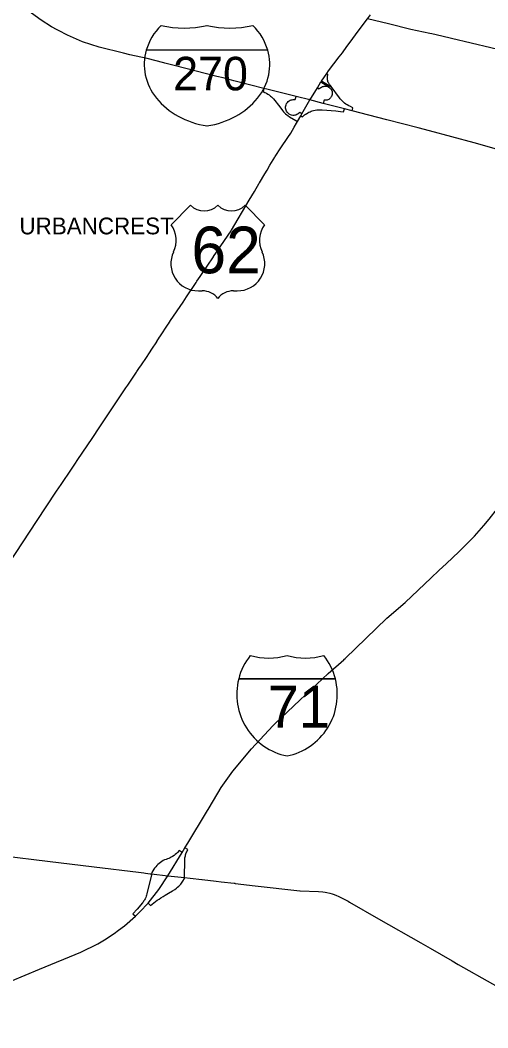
# Model space of a CAD drawing. Extents: x -1146 to -445, y -1283 to -822.
# Drawn here: x -959.3 to -924.4, y -1179.7 to -1104.6 of the extents above; entities that cross this region are included whole.
import ezdxf

# ---------------------------------------------------------------- set-up
doc = ezdxf.new("R2010")
doc.units = 0
for name, color, linetype in [('GM_X_Corporation_Text', 7, 'Continuous'), ('GM_X_Interchange_Ramps', 7, 'Continuous'), ('GM_X_Interstate_Route', 7, 'Continuous'), ('GM_X_Interstate_Shield', 7, 'Continuous'), ('GM_X_State_Route', 7, 'Continuous'), ('GM_X_Township', 7, 'Continuous'), ('GM_X_US_Route', 7, 'Continuous'), ('GM_X_US_Shield', 7, 'Continuous')]:
    doc.layers.add(name, color=color, linetype=linetype)

msp = doc.modelspace()

# ---------------------------------------------------------------- linework, layer by layer
at = {"layer": 'GM_X_Interchange_Ramps'}
for points in [[(-934.577, -1111.334), (-934.518, -1111.105), (-934.687, -1111.022), (-934.822, -1110.957), (-934.929, -1110.897), (-935.031, -1110.833), (-935.125, -1110.764), (-935.208, -1110.697), (-935.287, -1110.627), (-935.386, -1110.527), (-935.45, -1110.456), (-935.513, -1110.378), (-936.138, -1109.534), (-936.194, -1109.458), (-936.261, -1109.375), (-936.313, -1109.289), (-936.345, -1109.221), (-936.369, -1109.158), (-936.386, -1109.096), (-936.398, -1109.04), (-936.407, -1108.961), (-936.409, -1108.886), (-936.403, -1108.799), (-936.37, -1108.618), (-936.453, -1108.558)], [(-941.149, -1109.671), (-941.211, -1109.908), (-941.071, -1109.97), (-940.958, -1110.029), (-940.856, -1110.09), (-940.763, -1110.153), (-940.657, -1110.234), (-940.587, -1110.295), (-940.514, -1110.365), (-940.431, -1110.454), (-939.969, -1111.047), (-939.767, -1111.309), (-939.687, -1111.405), (-939.614, -1111.484), (-939.535, -1111.557), (-939.447, -1111.63), (-939.373, -1111.685), (-939.235, -1111.785), (-938.77, -1112.068), (-938.647, -1112.141)], [(-937.158, -1109.621), (-937.021, -1109.706), (-936.971, -1109.658), (-936.91, -1109.612), (-936.845, -1109.572), (-936.772, -1109.536), (-936.706, -1109.515), (-936.643, -1109.504), (-936.572, -1109.5), (-936.491, -1109.507), (-936.411, -1109.527), (-936.355, -1109.549), (-936.298, -1109.581), (-936.243, -1109.62), (-936.197, -1109.663), (-936.159, -1109.707), (-936.125, -1109.757), (-936.094, -1109.818), (-936.068, -1109.894), (-936.055, -1109.958), (-936.051, -1110.053), (-936.059, -1110.121), (-936.08, -1110.202), (-936.111, -1110.274), (-936.146, -1110.33), (-936.187, -1110.382), (-936.229, -1110.424), (-936.268, -1110.455), (-936.317, -1110.487), (-936.377, -1110.516), (-936.439, -1110.537), (-936.483, -1110.547), (-936.54, -1110.555), (-936.659, -1110.555), (-936.719, -1110.793)], [(-936.897, -1109.169), (-936.82, -1109.222), (-936.277, -1109.545), (-936.298, -1109.581)], [(-936.138, -1109.534), (-936.159, -1109.55), (-936.791, -1109.173), (-936.865, -1109.122)], [(-938.312, -1111.557), (-938.463, -1111.467), (-938.593, -1111.569), (-938.688, -1111.625), (-938.762, -1111.654), (-938.838, -1111.673), (-938.918, -1111.682), (-939.002, -1111.679), (-939.08, -1111.666), (-939.161, -1111.64), (-939.265, -1111.586), (-939.344, -1111.524), (-939.415, -1111.445), (-939.466, -1111.365), (-939.499, -1111.288), (-939.52, -1111.217), (-939.53, -1111.148), (-939.531, -1111.046), (-939.519, -1110.962), (-939.494, -1110.88), (-939.456, -1110.799), (-939.391, -1110.707), (-939.331, -1110.646), (-939.255, -1110.589), (-939.18, -1110.55), (-939.114, -1110.525), (-939.042, -1110.508), (-938.969, -1110.5), (-938.815, -1110.506), (-938.75, -1110.271)], [(-938.401, -1111.712), (-938.279, -1111.784), (-938.186, -1111.701), (-938.119, -1111.647), (-938.051, -1111.597), (-937.984, -1111.552), (-937.881, -1111.49), (-937.787, -1111.442), (-937.705, -1111.404), (-937.626, -1111.372), (-937.544, -1111.344), (-937.451, -1111.317), (-937.322, -1111.287), (-937.205, -1111.268), (-937.063, -1111.256), (-936.936, -1111.254), (-936.809, -1111.26), (-935.789, -1111.352), (-935.424, -1111.384), (-935.204, -1111.426), (-935.141, -1111.186)], [(-947.251, -1166.639), (-947.465, -1166.508), (-947.599, -1166.652), (-947.676, -1166.726), (-947.762, -1166.8), (-947.857, -1166.872), (-947.969, -1166.947), (-948.058, -1166.998), (-948.152, -1167.046), (-948.251, -1167.09), (-948.353, -1167.129), (-948.447, -1167.16), (-948.555, -1167.203), (-948.654, -1167.25), (-948.763, -1167.311), (-948.867, -1167.379), (-948.965, -1167.454), (-949.062, -1167.539), (-949.141, -1167.62), (-949.218, -1167.709), (-949.301, -1167.822), (-949.361, -1167.891), (-949.438, -1168.006), (-949.508, -1168.129), (-949.537, -1168.241)], [(-947.073, -1168.499), (-947.069, -1168.386), (-947.058, -1167.328), (-947.056, -1167.218), (-947.05, -1167.128), (-947.041, -1167.054), (-947.026, -1166.964), (-947.01, -1166.889), (-946.991, -1166.814), (-946.968, -1166.741), (-946.942, -1166.666), (-946.912, -1166.592), (-946.835, -1166.424), (-947.046, -1166.295)], [(-949.537, -1168.241), (-949.546, -1168.32), (-949.88, -1169.737), (-949.907, -1169.828), (-949.935, -1169.905), (-949.971, -1169.993), (-950.017, -1170.09), (-950.056, -1170.163), (-950.092, -1170.225), (-950.126, -1170.278), (-950.166, -1170.337), (-950.205, -1170.39), (-950.6, -1170.882), (-950.922, -1171.216), (-950.734, -1171.403)], [(-949.792, -1170.423), (-949.621, -1170.594), (-949.487, -1170.488), (-949.367, -1170.396), (-949.227, -1170.294), (-949.102, -1170.205), (-948.971, -1170.115), (-948.832, -1170.023), (-948.665, -1169.918), (-948.517, -1169.828), (-948.389, -1169.753), (-948.264, -1169.682), (-947.977, -1169.511), (-947.8, -1169.405), (-947.679, -1169.317), (-947.589, -1169.243), (-947.495, -1169.154), (-947.422, -1169.077), (-947.358, -1169.002), (-947.301, -1168.928), (-947.189, -1168.777), (-947.081, -1168.575), (-947.073, -1168.499)]]:
    msp.add_lwpolyline(points, dxfattribs=at)
at = {"layer": 'GM_X_Interstate_Route'}
for points in [[(-956.563, -1105.311), (-957.01, -1105.076), (-957.775, -1104.578), (-958.499, -1104.045), (-959.23, -1103.43), (-959.413, -1103.252)], [(-951.142, -1107.157), (-951.627, -1107.051), (-953.431, -1106.586), (-954.68, -1106.197), (-955.794, -1105.705), (-956.477, -1105.356), (-956.563, -1105.311)], [(-948.546, -1107.78), (-948.607, -1107.764), (-949.866, -1107.436), (-951.142, -1107.157)], [(-943.923, -1108.959), (-944.19, -1108.89), (-944.667, -1108.768), (-947.839, -1107.964), (-948.546, -1107.78)], [(-943.394, -1109.095), (-943.923, -1108.959)], [(-940.931, -1109.726), (-941.149, -1109.671), (-942.131, -1109.42), (-943.394, -1109.095)], [(-937.723, -1110.53), (-938.75, -1110.271), (-940.931, -1109.726)], [(-918.68, -1116.588), (-919.128, -1116.32), (-920.698, -1115.452), (-921.421, -1115.142), (-922.643, -1114.621), (-923.8, -1114.196), (-925.452, -1113.725), (-928.801, -1112.823), (-929.653, -1112.604), (-931.972, -1112.008), (-933.318, -1111.662), (-934.577, -1111.334), (-935.141, -1111.186), (-936.719, -1110.793), (-937.723, -1110.53)], [(-924.752, -1142.273), (-924.336, -1141.79), (-923.11, -1140.191), (-922.672, -1139.564), (-921.629, -1137.894), (-921.487, -1137.641)], [(-928.092, -1145.619), (-927.535, -1145.096), (-926.609, -1144.216), (-925.429, -1143.058), (-924.752, -1142.273)], [(-935.194, -1152.265), (-935.094, -1152.176), (-931.983, -1149.176), (-930.614, -1148.014), (-928.67, -1146.162), (-928.092, -1145.619)], [(-940.482, -1157.202), (-940.421, -1157.135), (-940.313, -1157.017), (-938.472, -1155.287), (-936.354, -1153.288), (-935.196, -1152.267), (-935.194, -1152.265)], [(-945.234, -1163.319), (-944.328, -1161.809), (-943.473, -1160.577), (-942.069, -1158.924), (-940.482, -1157.202)], [(-946.837, -1165.952), (-945.428, -1163.642), (-945.234, -1163.319)], [(-948.312, -1168.38), (-947.251, -1166.639), (-947.046, -1166.295), (-946.837, -1165.952)], [(-951.99, -1172.446), (-951.542, -1172.113), (-950.734, -1171.403), (-950.396, -1171.069), (-949.792, -1170.423), (-948.991, -1169.405), (-948.312, -1168.38)], [(-968.533, -1179.721), (-968.41, -1179.67), (-965.26, -1178.386), (-961.115, -1176.691), (-957.891, -1175.351), (-954.804, -1174.074), (-953.551, -1173.453), (-952.931, -1173.094), (-952.659, -1172.914)], [(-952.659, -1172.914), (-952.311, -1172.684), (-951.99, -1172.446)]]:
    msp.add_lwpolyline(points, dxfattribs=at)
at = {"layer": 'GM_X_Interstate_Shield'}
for p, q in [((-940.864, -1106.804), (-949.929, -1106.804)), ((-940.864, -1106.804), (-949.929, -1106.804)), ((-943.03, -1153.705), (-935.816, -1153.705)), ((-935.816, -1153.705), (-943.03, -1153.705)), ((-935.816, -1153.705), (-943.03, -1153.705))]:
    msp.add_line(p, q, dxfattribs=at)
for centre, start, end in [((-938.486, -1154.854), 141.66896, 165.80665), ((-940.793, -1147.464), 253.00908, 286.99093), ((-938.053, -1147.464), 253.00908, 286.99093), ((-940.361, -1154.854), 14.19335, 38.33104), ((-938.486, -1154.854), 165.80665, 258.46304), ((-940.361, -1154.854), 281.53696, 14.19335)]:
    msp.add_arc(centre, 4.688, start, end, dxfattribs=at)
for centre, start_param, end_param in [((-944.224, -1107.875), 2.47259, 2.911027), ((-947.108, -1100.485), 4.415841, 5.008937), ((-943.684, -1100.485), 4.415841, 5.008937), ((-946.568, -1107.875), 0.230566, 0.669003), ((-944.224, -1107.875), 2.911027, 4.511031), ((-946.568, -1107.875), 4.913747, 6.513751)]:
    msp.add_ellipse(centre, major_axis=(5.859, 0), ratio=0.8, start_param=start_param, end_param=end_param, dxfattribs=at)
at = {"layer": 'GM_X_State_Route'}
for points in [[(-968.164, -1166.022), (-968.04, -1166.038), (-961.891, -1166.75), (-960.545, -1166.906), (-957.293, -1167.291), (-953.811, -1167.708), (-950.505, -1168.12), (-950.108, -1168.165)], [(-950.108, -1168.165), (-949.977, -1168.18), (-949.647, -1168.226)], [(-949.647, -1168.226), (-949.537, -1168.241), (-948.312, -1168.38), (-947.073, -1168.499), (-946.659, -1168.565)], [(-946.659, -1168.565), (-945.793, -1168.663), (-945.755, -1168.668)], [(-945.755, -1168.668), (-944.722, -1168.792)], [(-944.722, -1168.792), (-944.345, -1168.837), (-944.335, -1168.838)], [(-944.335, -1168.838), (-943.36, -1168.938), (-943.309, -1168.944), (-943.3, -1168.945)], [(-943.3, -1168.945), (-941.803, -1169.121), (-938.48, -1169.502), (-938.442, -1169.506), (-937.065, -1169.548), (-936.762, -1169.578), (-936.575, -1169.603)], [(-936.575, -1169.603), (-936.446, -1169.619), (-936.229, -1169.678), (-936.054, -1169.73), (-935.904, -1169.778), (-935.73, -1169.843), (-935.614, -1169.895), (-935.219, -1170.102)], [(-935.219, -1170.102), (-934.867, -1170.287)], [(-934.867, -1170.287), (-934.771, -1170.337), (-932.602, -1171.587), (-929.445, -1173.37), (-928.757, -1173.791), (-927.098, -1174.721), (-926.651, -1174.988), (-924.094, -1176.438), (-922.913, -1177.105)]]:
    msp.add_lwpolyline(points, dxfattribs=at)
at = {"layer": 'GM_X_Township'}
msp.add_lwpolyline([(-921.29, -1107.327), (-927.148, -1105.948), (-927.883, -1105.775), (-928.631, -1105.599), (-928.778, -1105.565), (-930.186, -1105.266), (-931.853, -1104.841), (-933.424, -1104.471)], dxfattribs=at)
at = {"layer": 'GM_X_US_Route'}
for points in [[(-934.041, -1105.296), (-933.424, -1104.471), (-933.2, -1104.178)], [(-934.957, -1106.533), (-934.801, -1106.312), (-934.041, -1105.296)], [(-935.534, -1107.324), (-935.295, -1107.01), (-934.957, -1106.533)], [(-937.61, -1110.348), (-937.158, -1109.621), (-936.897, -1109.169), (-936.865, -1109.122), (-936.453, -1108.558), (-936.32, -1108.352), (-935.534, -1107.324)], [(-938.712, -1112.247), (-938.647, -1112.141), (-938.401, -1111.712), (-938.312, -1111.557), (-937.723, -1110.53), (-937.61, -1110.348)], [(-939.36, -1113.331), (-939.137, -1113.003), (-938.895, -1112.546), (-938.712, -1112.247)], [(-945.852, -1123.608), (-944.923, -1122.221), (-944.908, -1122.199), (-943.594, -1120.277), (-943.568, -1120.234), (-942.244, -1118.007), (-941.851, -1117.345), (-941.494, -1116.744), (-941.478, -1116.717), (-941.085, -1116.05), (-940.916, -1115.765), (-940.703, -1115.402), (-940.344, -1114.793), (-940.307, -1114.737), (-939.88, -1114.098), (-939.36, -1113.331)], [(-948.279, -1127.233), (-948.111, -1126.981), (-947.183, -1125.596), (-946.923, -1125.208), (-946.203, -1124.132), (-946.146, -1124.047)], [(-946.146, -1124.047), (-945.909, -1123.692), (-945.852, -1123.608)], [(-949.143, -1128.563), (-949.133, -1128.548), (-948.939, -1128.219), (-948.917, -1128.187), (-948.287, -1127.245), (-948.279, -1127.233)], [(-950.62, -1130.784), (-950.472, -1130.563), (-950.279, -1130.272), (-949.922, -1129.734), (-949.696, -1129.394), (-949.507, -1129.114), (-949.143, -1128.563)], [(-953.386, -1134.898), (-952.892, -1134.167), (-952.255, -1133.2), (-951.848, -1132.584), (-951.443, -1131.993), (-951.314, -1131.791), (-950.648, -1130.826), (-950.62, -1130.784)], [(-955.256, -1137.689), (-955.021, -1137.329), (-953.972, -1135.767), (-953.386, -1134.898)], [(-956.22, -1139.122), (-955.55, -1138.139), (-955.256, -1137.689)], [(-963.272, -1149.761), (-958.113, -1141.955), (-956.627, -1139.709), (-956.283, -1139.216), (-956.22, -1139.122)]]:
    msp.add_lwpolyline(points, dxfattribs=at)
at = {"layer": 'GM_X_US_Shield'}
for p, q in [((-946.618, -1118.38), (-948.068, -1119.83)), ((-941.107, -1119.83), (-942.557, -1118.38)), ((-946.038, -1124.76), (-945.748, -1124.76)), ((-943.427, -1124.76), (-943.137, -1124.76))]:
    msp.add_line(p, q, dxfattribs=at)
for centre, radius, start, end in [((-945.603, -1117.344), 1.45, 225.573, 314.427), ((-943.572, -1117.344), 1.45, 225.573, 314.427), ((-949.731, -1120.994), 2.03, 334.54712, 35.00093), ((-939.444, -1120.994), 2.03, 144.99907, 205.45288), ((-946.06, -1122.73), 2.03, 154.83192, 270.63826), ((-943.115, -1122.73), 2.03, 269.36174, 25.16808), ((-945.748, -1126.211), 1.45, 36.8699, 90), ((-943.427, -1126.211), 1.45, 90, 143.1301)]:
    msp.add_arc(centre, radius, start, end, dxfattribs=at)

# ---------------------------------------------------------------- texts
at = {"layer": 'GM_X_Corporation_Text'}
msp.add_text('URBANCREST', height=1.25, rotation=0.00001, dxfattribs=at).set_placement((-959.39, -1120.549))
at = {"layer": 'GM_X_Interstate_Shield'}
for s, height, p in [('270', 2.5, (-947.921, -1109.812)), ('71', 3.125, (-940.867, -1157.337))]:
    msp.add_text(s, height=height, dxfattribs=at).set_placement(p)
at = {"layer": 'GM_X_US_Shield'}
msp.add_text('62', height=3.4805, dxfattribs=at).set_placement((-946.558, -1123.455))

doc.saveas('drawing.dxf')
